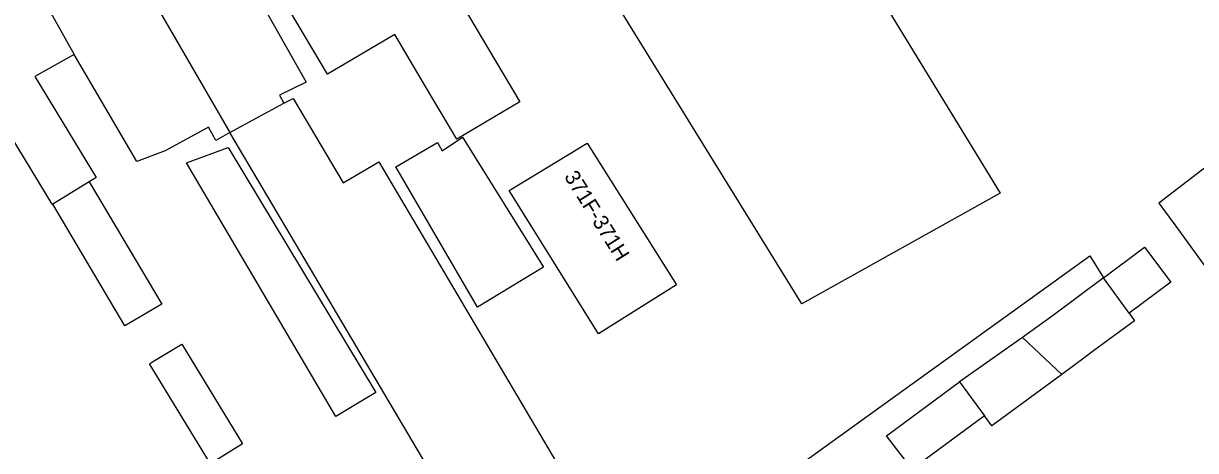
# Model space of a CAD drawing. Extents: x 159822 to 160765, y 380693 to 381634.
# Drawn here: x 159932.4 to 160009.6, y 381446.3 to 381474.4 of the extents above; entities that cross this region are included whole.
import ezdxf

# ---------------------------------------------------------------- set-up
doc = ezdxf.new("R2010")
doc.units = 0
for name, color, linetype in [('IMGEO_Pand', 7, 'Continuous'), ('IMGEO_Pand_nummerreeks', 7, 'Continuous'), ('IMGEO_Voetpad_open', 7, 'Continuous')]:
    doc.layers.add(name, color=color, linetype=linetype)

msp = doc.modelspace()

# ---------------------------------------------------------------- linework, layer by layer
at = {"layer": 'IMGEO_Pand'}
for points in [[(159952.629, 381490.261), (159955.179, 381485.96), (159963.025, 381472.729), (159965.093, 381469.241), (159960.942, 381466.779), (159958.874, 381470.267), (159956.844, 381473.69), (159952.421, 381471.068), (159948.483, 381477.709), (159946.592, 381480.898), (159944.042, 381485.199)], [(159943.094, 381484.616), (159945.573, 381480.173), (159946.58, 381478.421), (159951.006, 381470.546), (159949.258, 381469.678), (159949.545, 381469.151)], [(159937.151, 381482.476), (159945.986, 381467.216)], [(159931.762, 381479.45), (159935.718, 381472.36)], [(159989.504, 381475.275), (159989.4, 381475.217), (159996.739, 381463.236), (159983.663, 381455.926), (159969.908, 381478.266), (159969.777, 381478.193)], [(159934.303, 381462.509), (159934.277, 381462.493), (159930.15, 381469.253), (159929.941, 381469.137), (159928.43, 381471.845), (159925.993, 381476.211)], [(159935.718, 381472.36), (159933.119, 381470.91), (159937.177, 381464.264), (159936.71, 381463.979)], [(159945.986, 381467.216), (159945.046, 381466.705), (159944.571, 381467.579), (159941.709, 381466.023), (159939.859, 381465.323), (159937.807, 381468.81), (159935.718, 381472.36)], [(159949.545, 381469.151), (159950.143, 381469.476), (159953.438, 381463.902), (159955.786, 381465.29), (159972.361, 381437.246)], [(159945.986, 381467.216), (159949.545, 381469.151)], [(159970.261, 381435.772), (159966.045, 381433.28), (159945.986, 381467.216)], [(159966.645, 381458.354), (159962.305, 381455.708), (159956.907, 381464.969), (159959.659, 381466.573), (159959.977, 381466.027), (159961.3, 381466.927), (159966.645, 381458.354)], [(159975.413, 381457.178), (159970.271, 381453.942), (159964.382, 381463.407), (159969.532, 381466.524), (159975.413, 381457.178)], [(159943.118, 381465.219), (159945.873, 381466.244), (159955.607, 381450.084), (159952.961, 381448.497), (159943.118, 381465.219)], [(159936.71, 381463.979), (159941.495, 381455.91), (159939.068, 381454.471), (159934.303, 381462.509)], [(159936.71, 381463.979), (159934.303, 381462.509)], [(160003.553, 381457.635), (160006.263, 381459.657), (160007.983, 381457.351), (160005.243, 381455.307)], [(160003.553, 381457.635), (160000.265, 381455.184), (159998.208, 381453.721)], [(160005.243, 381455.307), (160003.553, 381457.635)], [(160005.243, 381455.307), (160005.601, 381454.814), (160002.906, 381452.827), (160002.337, 381452.407), (160000.804, 381451.277)], [(159940.678, 381451.978), (159940.949, 381452.143), (159942.814, 381453.278), (159946.822, 381446.69), (159944.698, 381445.379), (159940.678, 381451.978)], [(159998.208, 381453.721), (159994.07, 381450.779)], [(159998.208, 381453.721), (160000.804, 381451.277)], [(160000.804, 381451.277), (159996.206, 381447.885), (159995.711, 381448.555)], [(159990.935, 381445.032), (159989.251, 381447.224), (159994.07, 381450.779)], [(159994.07, 381450.779), (159995.711, 381448.555)], [(159995.711, 381448.555), (159990.935, 381445.032)]]:
    msp.add_lwpolyline(points, dxfattribs=at)
at = {"layer": 'IMGEO_Voetpad_open'}
for points in [[(160012.867, 381466.922), (160007.209, 381462.575), (160008.252, 381461.14), (160017.286, 381448.698)], [(159972.361, 381437.246), (159987.953, 381448.493), (160002.662, 381459.103), (160003.553, 381457.635)]]:
    msp.add_lwpolyline(points, dxfattribs=at)

# ---------------------------------------------------------------- texts
at = {"layer": 'IMGEO_Pand_nummerreeks'}
msp.add_text('371F-371H', height=1, rotation=301.98229, dxfattribs=at).set_placement((159967.981, 381464.324))

doc.saveas('drawing.dxf')
